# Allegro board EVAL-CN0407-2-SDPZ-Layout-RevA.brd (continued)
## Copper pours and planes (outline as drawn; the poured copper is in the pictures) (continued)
+VIN_PROTECTED on TOP (solid shape): 142.9,46.3 142.9,44.73 142.75,44.58 142.75,44.32 142.93,44.14 143.44,44.14 143.44,43.26 143.34,43.15 141.28,43.15 141.25,43.13 140.59,43.13 140.59,43.79 141.35,44.55 141.35,46.46 141.74,46.84 142.37,46.84
-2.5VA on L3_POWER: 115.04,0.64 115.04,6.83 113.77,8.1 112.5,6.83 112.5,2.89 107.95,2.89 107.95,13.94 113.8,13.94 113.8,35.79 128.65,35.79 128.65,26.93 121.54,19.82 121.54,0.64
-5.8V_RAW on TOP (solid shape): 141.74,41.68 141.74,40.87 142.12,40.49 142.12,39.06 141.71,38.66 139.7,38.66 139.65,38.71 139.65,39.62 139.81,39.78 140.9,39.78 140.97,39.85 140.97,41.38 140.31,42.04 140.44,42.16 141.25,42.16
-5.8V_RAW on L3_POWER: 133.13,35.79 132.59,36.33 132.59,47.31 133.26,47.98 141.96,47.98 142.24,47.69 142.24,36.45 141.58,35.79
AGND on TOP (solid shape): 147.83,46.58 147.83,36.55 146.94,35.66 139.83,35.66 139.32,36.17 139.32,37.67 139.63,37.97 142.01,37.97 142.62,38.58 146.18,38.58 146.43,38.84 146.43,42.39 145.57,43.26 144.53,43.26 144.53,44.14 144.76,44.37 144.76,46.81 145.01,47.06 147.36,47.06
AGND on TOP: 3.78,40.01 3.78,59.66 3.77,59.67 88.43,59.67 88.43,10.7 88.4,10.67 3.81,10.67 3.81,24.51 20.66,24.51 20.91,24.77 20.91,39.75 20.66,40.01 ; 1 cut-out
AGND on L2_GND: 0.64,0.64 0.64,24.6 19.38,24.6 20.37,25.01 20.78,26 20.78,38.42 20.37,39.41 19.38,39.82 0.64,39.82 0.64,68.83 96.14,68.83 96.14,52.9 97.25,51.79 126.59,51.79 128.65,49.73 128.65,26.93 121.92,20.2 121.92,19.88 122.15,19.66 122.46,19.66 129.42,26.61 129.42,50.04 126.91,52.55 97.57,52.55 96.9,53.22 96.9,68.83 126.11,68.83 126.11,56.33 129.51,52.93 133.32,52.93 136.37,49.88 149.1,49.88 149.1,34.01 144.15,34.01 144.15,0.64 115.04,0.64 115.04,6.83 113.77,8.1 112.5,6.83 112.5,2.89 107.95,2.89 107.95,13.97 112.14,13.97 113.41,15.24 112.14,16.51 106.68,16.51 105.79,16.14 105.41,15.24 105.41,0.64
AGND on L3_POWER: 0.64,0.64 0.64,24.6 19.38,24.6 20.37,25.01 20.78,26 20.78,38.42 20.37,39.41 19.38,39.82 0.64,39.82 0.64,68.83 96.14,68.83 96.14,52.9 97.25,51.79 126.59,51.79 128.65,49.73 128.65,36.55 113.03,36.55 113.03,16.48 112.4,16.48 112.27,16.5 112.14,16.51 106.68,16.51 105.79,16.14 105.41,15.24 105.41,0.64
AGND on L3_POWER: 122.3,0.64 122.3,6.96 124.94,6.96 125.35,6.55 125.35,0.64
AGND on L3_POWER: 126.11,0.64 126.11,6.86 125.26,7.72 122.3,7.72 122.3,19.5 129.42,26.61 129.42,50.04 126.91,52.55 97.57,52.55 96.9,53.22 96.9,68.83 126.11,68.83 126.11,56.33 129.51,52.93 133.32,52.93 136.37,49.88 149.1,49.88 149.1,34.01 144.15,34.01 144.15,0.64 ; 1 cut-out
AGND2 on L2_GND, L3_POWER: 144.91,0.64 144.91,33.25 149.86,33.25 149.86,50.65 136.69,50.65 133.64,53.69 129.83,53.69 126.88,56.65 126.88,68.83 164.47,68.83 164.47,0.64 156.34,0.64 156.34,0.76 154.82,0.76 154.44,1.14 149.86,1.14 149.66,0.94 149.63,0.94 149.46,0.76 148.72,0.76 148.72,0.64
VGUARD on TOP (solid shape): 91.95,7.11 0.72,7.11 0.72,24.51 3.05,24.51 3.05,9.53 89.54,9.53 89.54,60.33 3.05,60.33 3.05,40.01 0.97,40.01 0.97,62.99 91.95,62.99

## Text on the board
BOTTOM: SECONDARY SIDE
User.Comments: SEE ASSY NOTE#8 | (4 PLACES) | SEE ASSY NOTE#6 | SEE ASSY NOTE#10 | (3 PLACES) | DETAIL X | SEE ASSY NOTE#7 | (6 PLACES) | SEE ASSY NOTE#9 | 7.    TEFLON FORK INSULATED SUPPORT (M027991) MUST BE PRESSED FIT ON PRIMARY SIDE | IN 6 LOCATIONS SPECIFIED BY  . FORKS SHOULD BE ORIENTED IN PARALLEL TO | LEFT SIDE OF THE BOARD. | 6.    FEEDBACK RESISTOR IS NOT INCLUDED IN BOM AND WILL BE INSTALLED BY ADI. | PRIMARY SIDE | 4 PAN HEAD SCREWS (M028002). | SECONDARY SIDE, FASTENED USING PAN HEAD SCREWS (M028002). | FACING DOWN AND MATE ENTRY ON LEFT EDGE. BOARD MUST BE FASTENED USING | 10.   SHIELD INSTALLATION INSTRUCTIONS: | 8.    KFSE-M3-3 BROACHING STANDOFFS (M028001) MUST BE PRESSED FIT ON PRIMARY SIDE. | 9.    M3 FEMALE THREADED HEX STANDOFFS (M028004) SHOULD BE INSTALLED ON | 9.    MEZZANINE BOARD (BR-045657) MOUNTED ON PRIMARY SIDE WITH SMA CONNECTOR | A.   MEZZANINE BOARD SHOULD BE INSTALLED PRIOR TO SHIELD INSTALLATION | B.   INSTALL SHIELD CLIP (M024387) IN 3 PLACES SPECIFIED. | C.   MOUNT SHIELD BOX (M028349) IN AREA DEFINED BY DETAIL X. | BOX MUST BE FASTENED USING SHIELD CLIPS. | SECONDARY SIDE
TOP: 08-045416 REV A Z
Ref Des/Assembly Top: SHIELD CLIP | M3 | BR-045657 | FEEDBACK RESISTOR | SMA
Ref Des/Silkscreen Top: SHIELD1 | CL1 | CL3 | OUTPUT | ELECTROMETER | ISOLATION | STATUS | DIGITAL | CL2 | TRIGGER | INPUT | EVAL-CN0407-2-SDPZ | DATA ACQUISITION BOARD | REV A Z | PRIMARY SIDE | POWER MANAGEMENT | ADC | SECTION | ISOLATED USB | INTERFACE | FEEDBACK RESISTOR
DIMENSION: " " | (2 PLACES) | SEE DETAIL B | (REF) | DETAIL B | DETAIL A | DIA MAX | +2/-0 MILS
PAGE_OUTLINE: M. RAMILO | P. NANEA | K. JABATAN | 15FEB17 | CUSTOMER EVALUATION Z | ADA4530-1R, AD7172-2
User.15: ROHS COMPLIANCE NOTE: | THE EU RoHS DIRECTIVE 2002/95/EC | HOMOGENOUS MATERIALS IN THIS BOARD SHALL BE COMPLIANT | 15.    BOARDS TO BE PANELIZED AND SHIPPED INTACT.
User.17: L2 GND | 08-      -07
User.18: L3 POWER | 08-      -08
User.45: FIGURE | SIZE | 12.0 | 35.0 | 40.0 | 60.0 | 65.0 | 24.0 | 28.0 | 43.0 | 63.0 | 71.0 | 125.0 | 158.0 | 165.0 | PLATED | NON-PLATED | FINISHED HOLES IN MILS | ALL UNITS ARE IN MILS | QTY | 279 | 1 | 12 | 2 | 9 | 8 | 6 | 4 | TOLERANCE/NOTES
